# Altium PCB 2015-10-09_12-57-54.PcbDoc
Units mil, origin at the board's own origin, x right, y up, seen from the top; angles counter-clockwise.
Board outline 3100 x 2300 mil, 4 copper layers (Top Layer, MidLayer1, MidLayer2, Bottom Layer); 26 components, 13 nets, 66 pads, 301 vias.
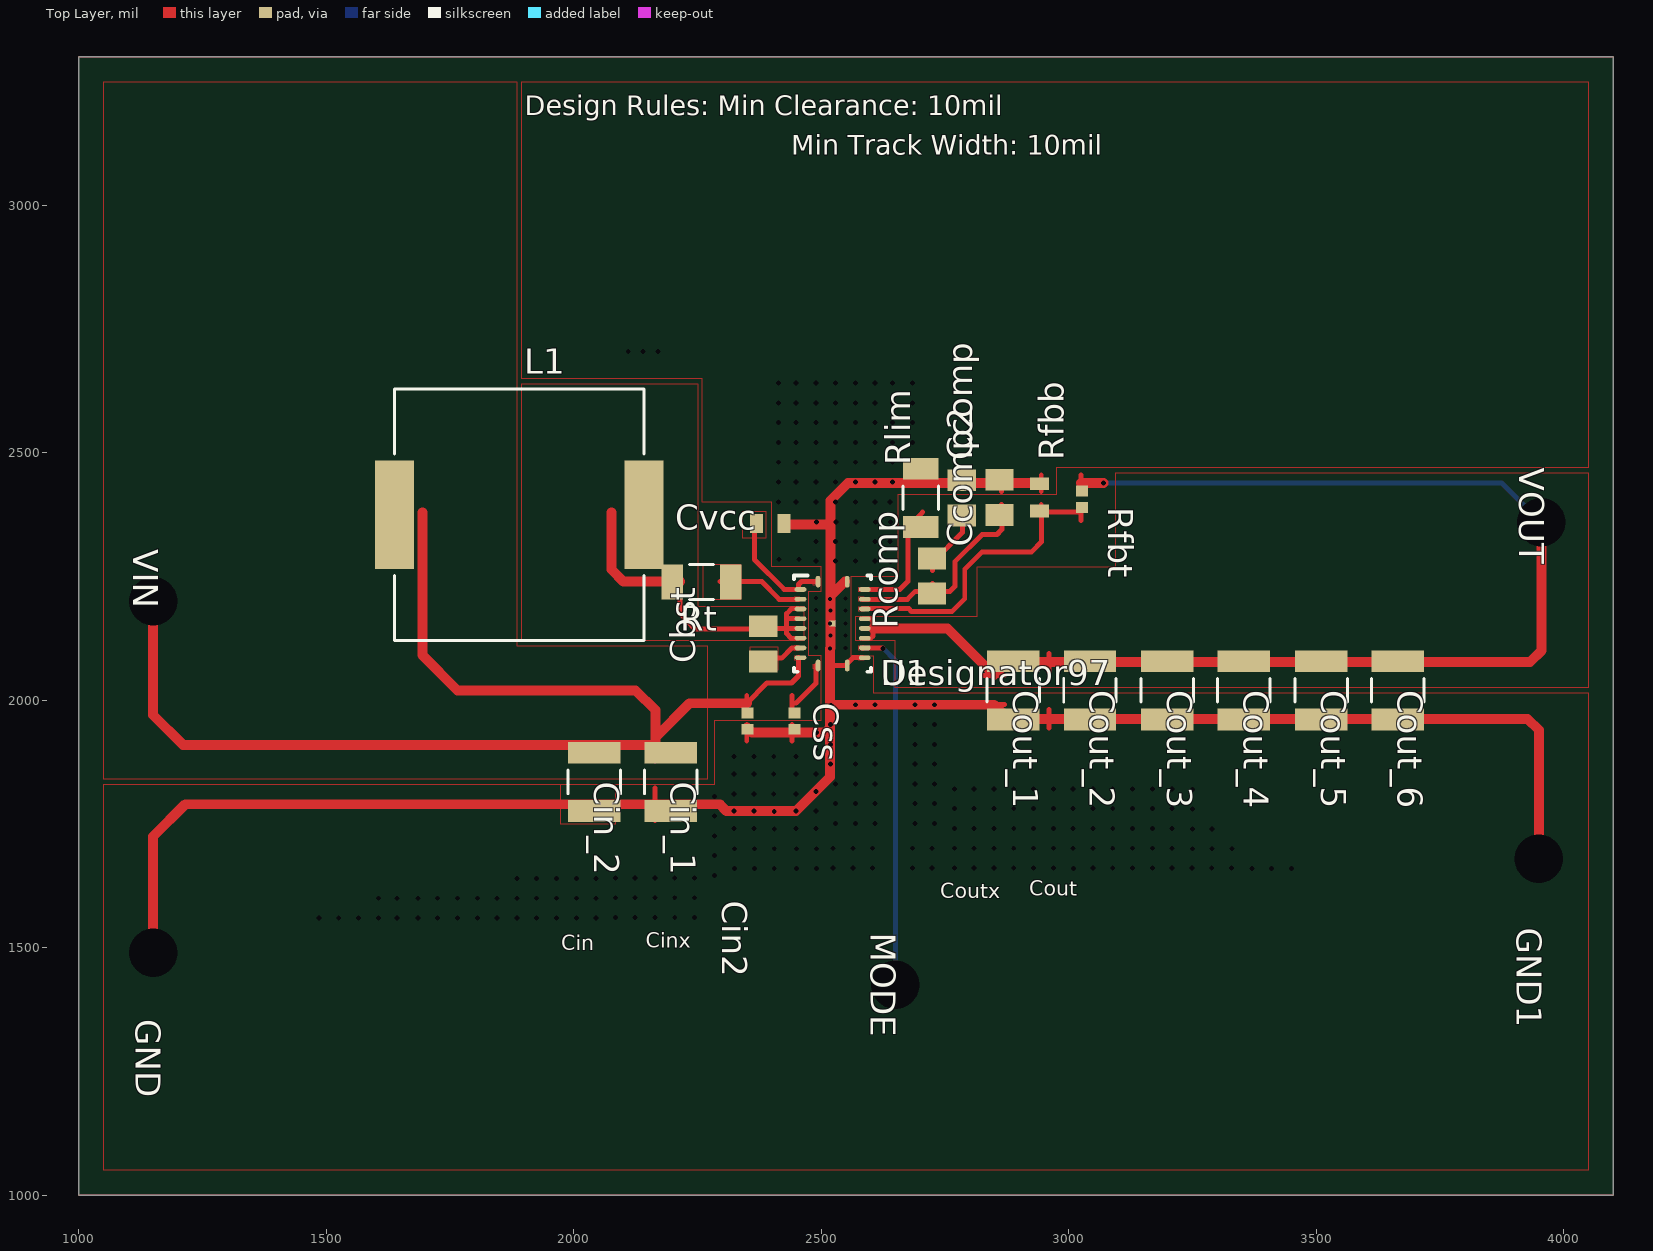
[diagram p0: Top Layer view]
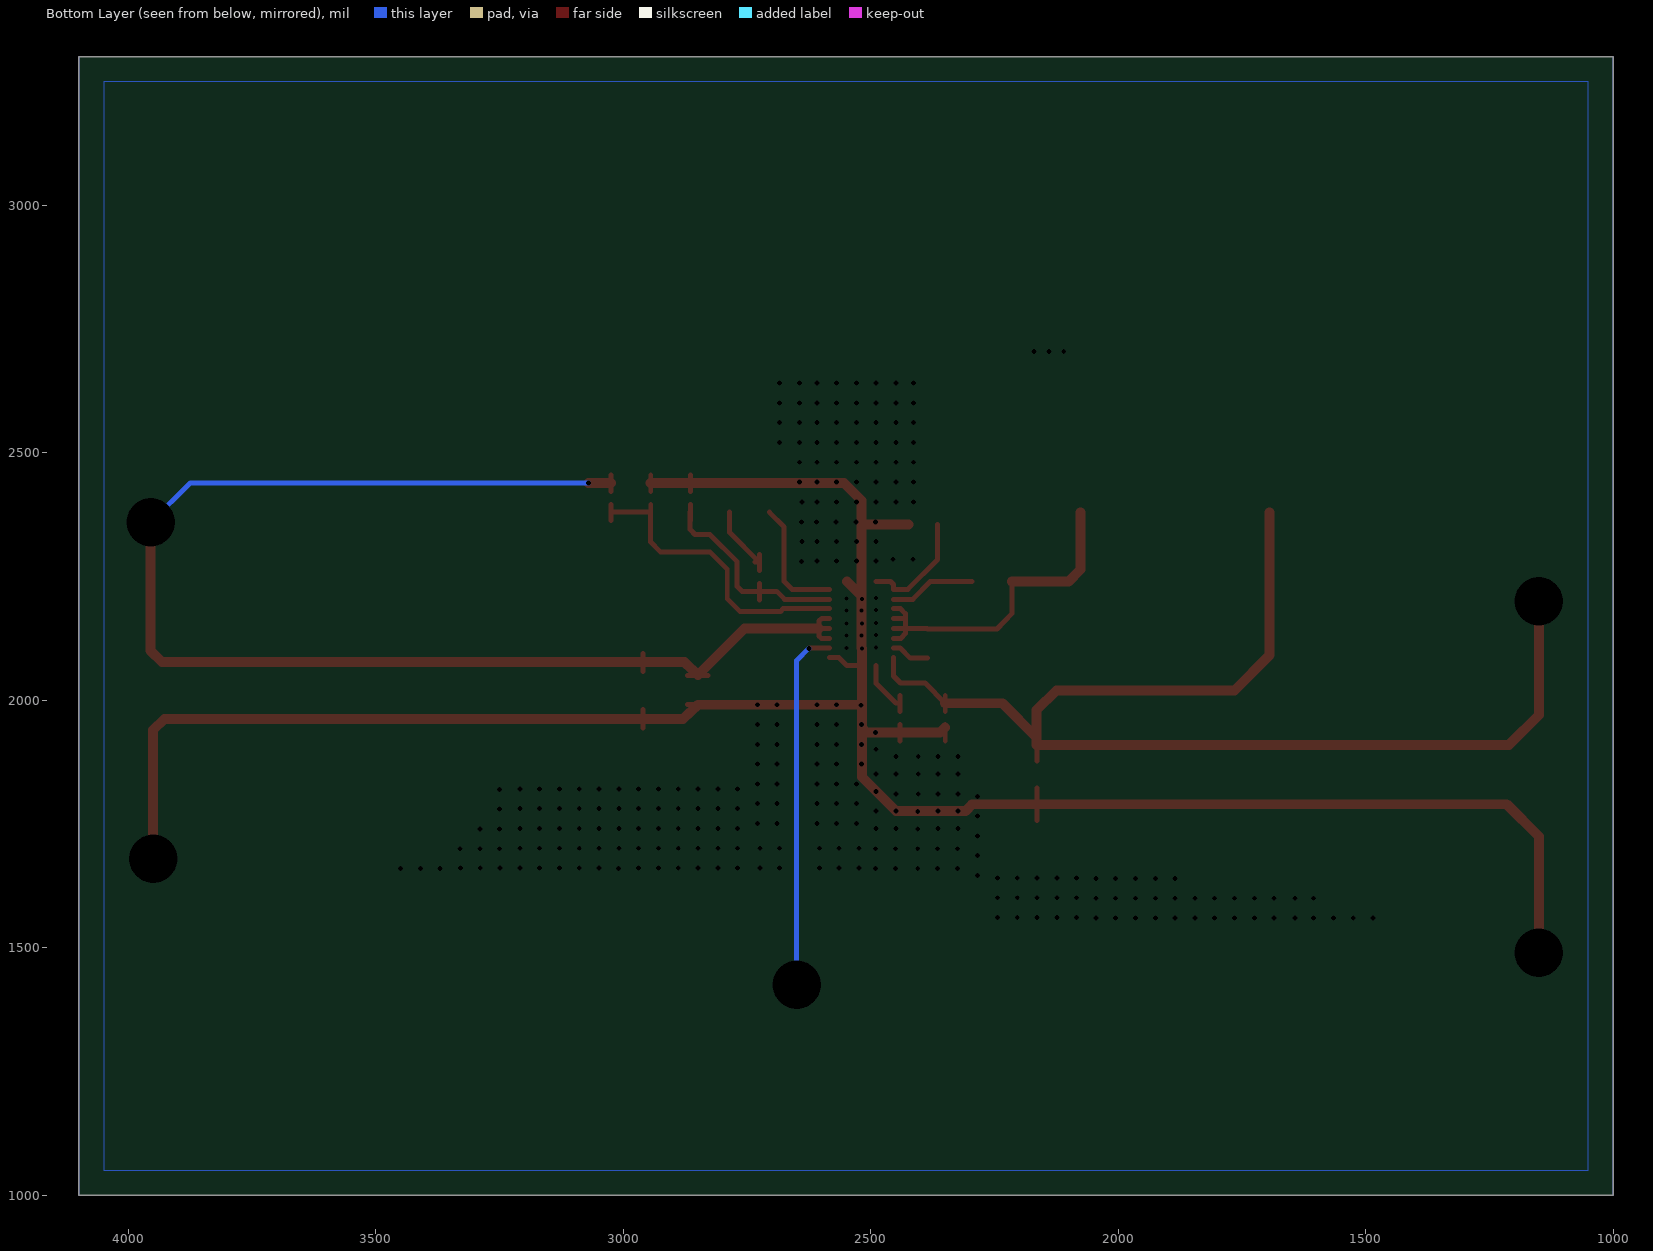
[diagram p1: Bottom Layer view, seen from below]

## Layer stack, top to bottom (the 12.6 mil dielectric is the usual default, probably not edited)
Top Layer: signal copper 1.4
Dielectric: core 12.6, FR-4, Dk 4.8
MidLayer1: signal copper 1.4
Dielectric: prepreg 12.6, FR-4, Dk 4.8
MidLayer2: signal copper 1.4
Dielectric: core 12.6, FR-4, Dk 4.8
Bottom Layer: signal copper 1.4

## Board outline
1000,1000 4100,1000 4100,3300 1000,3300

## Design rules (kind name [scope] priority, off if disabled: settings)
PlaneConnect [All] p0: scope1count=1 scope1_0_kind=Board scope1_0_value=Board scope2count=1 scope2_0_kind=Board scope2_0_value=Board commentlength=0 planeconnectstyle=Direct reliefexpansion=20 reliefentries=4 reliefconductorwidth=10 reliefairgap=10
PlaneConnect [All] p1: planeconnectstyle=Direct reliefexpansion=20 reliefentries=4 reliefconductorwidth=10 reliefairgap=10
PolygonConnect [All] p0: scope1count=1 scope1_0_kind=Board scope1_0_value=Board scope2count=1 scope2_0_kind=Board scope2_0_value=Board commentlength=0 connectstyle=Direct reliefconductorwidth=10 reliefentries=4 polygonreliefangle="90 Angle"
PolygonConnect [All] p1: connectstyle=Direct reliefconductorwidth=10 reliefentries=4 polygonreliefangle="90 Angle"

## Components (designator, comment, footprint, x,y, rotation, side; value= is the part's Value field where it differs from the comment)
Cbst "" 0805 2383,2114 r90 top
Ccomp "" 0805 2784,2409 r90 top
Ccomp2 "" 0805 2860,2410 r90 top
Cin2 "" 0402 2351,1958 r270 top
Cin_1 "" 1210 2196,1835 r270 top
Cin_2 "" 1210 2041,1835 r270 top
Cout_1 "" 1210 2888,2020 r270 top
Cout_2 "" 1210 3043,2020 r270 top
Cout_3 "" 1210 3199,2020 r270 top
Cout_4 "" 1210 3354,2020 r270 top
Cout_5 "" 1210 3510,2020 r270 top
Cout_6 "" 1210 3665,2020 r270 top
Css "" 0402 2446,1958 r270 top
Cvcc "" 1608 2397,2357 r0 top
GND "" TP-1502 1149,1490 r270 top
GND1 "" TP-1502 3948,1679 r270 top
L1 "" ETQP 1890,2375 r0 top
MODE "" TP-1502 2649,1425 r270 top
Rcomp "" 0805 2724,2251 r90 top
Rfbb "" 0603 2941,2410 r90 top
Rfbt "" 0402 3027,2406 r270 top
Rlim "" 1206 2701,2409 r90 top
Rt "" 1206 2258,2239 r0 top
U1 "" RHL0020A 2523,2155 r0 top
VIN "" TP-1502 1149,2198 r270 top
VOUT "" TP-1502 3953,2358 r270 top

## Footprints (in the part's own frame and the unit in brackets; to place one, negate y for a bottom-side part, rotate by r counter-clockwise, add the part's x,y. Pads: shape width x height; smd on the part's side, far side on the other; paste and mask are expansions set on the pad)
0402 [mil]
  rect 22x24 smd: 1(-16.5,0) 2(16.5,0)
0603 [mil]
  rect 26x38 smd: 1(-27.5,0) 2(27.5,0)
0805 [mil]
  rect 44x57 smd: 1(-35.5,0) 2(35.5,0)
1206 [mil]
  rect 44x71 smd: 1(-59,0) 2(59,0)
  silkscreen extent -24,-36 24,36
1210 [mil]
  rect 44x106 smd: 1(-59,0) 2(59,0)
  silkscreen extent -24,-53 24,53
1608 [mil]
  rect 26x38 smd: 1(-27.5,0) 2(27.5,0)
ETQP [mil]
  rect 79x220 smd: 1(-252,0) 2(252,0)
  silkscreen extent -252,-254 252,254
RHL0020A [mm]
  oval 0.24x0.6 smd: 1(-0.75,2.15) 10(-0.75,-2.15) 11(0.75,-2.15) 20(0.75,2.15)
  oval 0.6x0.24 smd: 2(-1.65,1.75) 3(-1.65,1.25) 4(-1.65,0.75) 5(-1.65,0.25) 6(-1.65,-0.25) 7(-1.65,-0.75) 8(-1.65,-1.25) 9(-1.65,-1.75) 12(1.65,-1.75) 13(1.65,-1.25) 14(1.65,-0.75) 15(1.65,-0.25) 16(1.65,0.25) 17(1.65,0.75) 18(1.65,1.25) 19(1.65,1.75)
  rect 0.3x0.3 smd: 21(0,0)
  silkscreen extent -1.98,-2.47 1.98,2.47
TP-1502 [mil]
  round 0 hole 32: 1(0,0)

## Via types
v1: diameter 0, hole 10, Top Layer to Bottom Layer, 281 vias
v2: diameter 0, hole 8, Top Layer to Bottom Layer, 15 vias
v3: diameter 0, hole 98, Top Layer to Bottom Layer, 5 vias

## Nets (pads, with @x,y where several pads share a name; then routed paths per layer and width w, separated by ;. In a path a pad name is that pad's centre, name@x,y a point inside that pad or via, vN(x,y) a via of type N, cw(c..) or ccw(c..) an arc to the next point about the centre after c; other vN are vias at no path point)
0: Ccomp2.2 Ccomp.2 Cin2.2 Cin_1.2 Cin_2.2 Cout_1.2 Cout_2.2 Cout_3.2 Cout_4.2 Cout_5.2 Cout_6.2 Css.2 Cvcc.2 GND1.1 GND.1 Rfbb.2 Rlim.2 U1.11 U1.12 U1.20 U1.21 | length 5042.3
  Top Layer w10: Cin_1.2@2164,1757 2164,1823 ; 2349.5,1918 Cin2.2@2349.5,1951 ; 2440.5,1918 Css.2@2440.5,1951 ; 2518,2070 2519,2070 2548,2070 2564,2086 U1.12@2583,2086 ; U1.21@2518.5,2153 U1.21@2518.5,2156 ; 2829,1991.5 2870,1991.5 ; 2864.5,2422 Ccomp2.2@2864.5,2455 ; 2944.5,2422 2944.5,2455 ; 2960,1944 2960,1981
  Top Layer w20: v3(1150,1490) 1150,1725 1215,1790 2030,1790 2165,1790 2295,1790 2308,1776 v1(2324,1776) v1(2364,1776) v1(2449,1776) 2518,1845 2518,1945 ; Cin2.2@2350,1945 2360,1935 2441,1935 2509,1935 2518,1945 ; Cvcc.2@2424,2355 2519,2355 ; U1.20@2548,2240 2519,2211 ; Rfbb.2@2945,2439 2865,2439 2785,2439 2705,2439 2554,2439 2519,2404 2519,2355 ; v3(3950,1680) 3950,1940 3927,1962 2960,1962 2879,1962 2849,1991 2521,1991 2518,1995 ; 2518,1945 2518,1995 ; 2518,1995 2518,2070 v2(2518,2105) 2519,2106 v2(2519,2131) v2(2519,2181) 2519,2211 ; 2519,2211 2519,2355
  other v1: 1485,1560 1525,1560 1565,1560 1605,1560 1643,1560 1685,1560 1725,1560 1765,1560 1805,1560 1845,1560 1885,1560 1925,1560 1965,1560 2005,1560 2045,1560 2084,1561 2124,1561 2164,1561 2204,1561 2244,1561 1605,1600 1643,1600 1685,1600 1725,1600 1765,1600 1805,1600 1845,1600 1885,1600 1925,1600 1965,1600 2005,1600 2045,1600 2084,1601 2124,1601 2164,1601 2204,1601 2244,1601 1885,1640 1925,1640 1965,1640 2005,1640 2045,1640 2084,1641 2124,1641 2164,1641 2204,1641 2244,1641 2284,1646 2325,1660 2365,1660 2405,1660 2450,1660 2490,1660 3010,1660 3370,1660 3410,1660 3450,1660 2524,1661 2564,1661 2604,1661 2684,1661 2724,1661 2769,1661 2809,1661 2849,1661 2889,1661 2929,1661 2969,1661 3049,1661 3089,1661 3129,1661 3169,1661 3209,1661 3249,1661 3289,1661 3329,1661 2284,1686 2325,1700 2365,1700 2405,1700 2450,1700 2490,1700 3250,1700 3290,1700 3330,1700 2524,1701 2564,1701 2604,1701 2684,1701 2724,1701 2769,1701 2809,1701 2849,1701 2889,1701 2929,1701 2969,1701 3009,1701 3049,1701 3089,1701 3129,1701 3169,1701 3209,1701 2284,1726 2405,1740 3250,1740 3290,1740 2324,1741 2364,1741 2449,1741 2489,1741 2769,1741 2809,1741 2849,1741 2889,1741 2929,1741 2969,1741 3009,1741 3049,1741 3089,1741 3129,1741 3169,1741 3209,1741 2529,1751 2569,1751 2609,1751 2689,1751 2729,1751 2284,1766 2405,1775 2489,1776 3250,1780 2769,1781 2809,1781 2849,1781 2889,1781 2929,1781 2969,1781 3009,1781 3049,1781 3089,1781 3129,1781 3169,1781 3209,1781 2529,1791 2569,1791 2609,1791 2689,1791 2729,1791 2284,1806 2324,1811 2364,1811 2404,1811 2449,1811 2489,1816 3250,1820 2769,1821 2809,1821 2849,1821 2889,1821 2929,1821 2969,1821 3009,1821 3049,1821 3089,1821 3129,1821 3169,1821 3209,1821 2529,1831 2569,1831 2609,1831 2689,1831 2729,1831 2324,1851 2364,1851 2404,1851 2449,1851 2489,1851 2519,1871 2569,1871 2609,1871 2689,1871 2729,1871 2324,1886 2364,1886 2404,1886 2449,1886 2489,1901 2519,1911 2569,1911 2609,1911 2689,1911 2729,1911 2490,1935 2519,1951 2569,1951 2609,1951 2689,1951 2729,1951 2520,1990 2569,1991 2609,1991 2689,1991 2729,1991 2640,2280 2489,2281 2529,2281 2569,2281 2609,2281 2415,2285 2455,2285 2489,2321 2529,2321 2569,2321 2609,2321 2639,2321 2490,2360 2530,2360 2570,2360 2610,2360 2640,2360 2414,2401 2449,2401 2489,2401 2529,2401 2569,2401 2609,2401 2639,2401 2414,2441 2449,2441 2489,2441 2529,2441 2569,2441 2609,2441 2644,2441 2414,2481 2449,2481 2489,2481 2529,2481 2569,2481 2609,2481 2644,2481 2414,2521 2449,2521 2489,2521 2529,2521 2569,2521 2609,2521 2644,2521 2684,2521 2414,2561 2449,2561 2489,2561 2529,2561 2569,2561 2609,2561 2644,2561 2684,2561 2414,2601 2449,2601 2489,2601 2529,2601 2569,2601 2609,2601 2644,2601 2684,2601 2414,2641 2449,2641 2489,2641 2529,2641 2569,2641 2609,2641 2644,2641 2684,2641 2110,2705 2140,2705 2170,2705
  other v2: 2549,2106 2489,2107 2549,2131 2489,2132 2518,2155 2549,2155 2489,2156 2549,2181 2489,2182 2518,2205 2549,2206 2489,2207
1: Cin2.1 Cin_1.1 Cin_2.1 L1.1 U1.9 VIN.1 | length 2637.5
  Top Layer w10: Cin_1.1@2164,1877 2164,1943 ; Cin2.1@2349.5,1977 2349.5,2010 ; 2350,1994 2390,2035 2440,2035 2454,2049 U1.9@2454,2086
  Top Layer w20: v3(1150,2200) 1150,1970 1210,1910 Cin_1.1@2165,1910 ; 1694,2380 1694,2091 1765,2020 2125,2020 2165,1980 Cin_1.1@2165,1910 ; 2350,1994 2234,1994 2165,1925 Cin_1.1@2165,1910
2: Cvcc.1 U1.1 U1.2 | length 232.3
  Top Layer w10: Cvcc.1@2365,2355 2365,2284 2425,2224 2454,2224 2454,2234 2460,2240 U1.1@2489,2240
3: Ccomp2.1 Rcomp.1 U1.18 | length 470.7
  Top Layer w10: U1.18@2583,2204 2674,2204 2690,2220 2725,2220 2760,2220 2770,2230 2770,2280 2825,2335 2855,2335 2865,2345 Ccomp2.1@2865,2380 ; Rcomp.1@2724.5,2203 Rcomp.1@2724.5,2236 ; Ccomp2.1@2864.5,2363 Ccomp2.1@2864.5,2396
5: Ccomp.1 Rcomp.2 | length 167.9
  Top Layer w10: 2724.5,2262 Rcomp.2@2724.5,2295 ; Rcomp.2@2734,2279 2725,2279 2785,2339 Ccomp.1@2785,2380
7: Rfbb.1 Rfbt.2 U1.17 | length 664.4
  Top Layer w10: U1.17@2583,2185 2677,2185 2682,2179 2764,2179 2790,2205 2790,2265 2825,2300 2925,2300 2945,2320 2945,2380 Rfbt.2@3025,2380 ; 2944.5,2363 2944.5,2396 ; 3024.5,2363 Rfbt.2@3024.5,2396
8: Cout_1.1 Cout_2.1 Cout_3.1 Cout_4.1 Cout_5.1 Cout_6.1 Rfbt.1 U1.14 U1.15 U1.16 VOUT.1 | length 2842.3
  Top Layer w10: U1.14@2583,2125 2600,2125 2605,2130 2605,2145 ; U1.15@2583,2145 2605,2145 ; U1.16@2583,2165 2599,2165 2605,2160 2605,2145 ; 2829,2050.5 2870,2050.5 ; 2960,2058 2960,2095 ; Rfbt.1@3024.5,2422 3024.5,2455
  Top Layer w20: 2605,2145 2755,2145 2849,2051 2876,2077 2960,2077 3932,2077 3955,2100 v3(3955,2360) ; 3025,2439 v1(3070,2439)
  Bottom Layer w10: v1(3070,2439) 3875,2439 v3(3955,2360)
9: Cbst.2 L1.2 Rt.1 U1.4 U1.5 U1.6 U1.7 | length 703.1
  Top Layer w10: Rt.1@2215,2240 2215,2175 2245,2144 2385,2144 2386,2145 2430,2145 ; U1.7@2454,2125 2439,2125 2430,2135 2430,2145 ; U1.6@2454,2145 2430,2145 ; U1.5@2454,2165 2430,2165 ; U1.4@2454,2185 2440,2185 2430,2175 2430,2165 ; 2430,2145 2430,2165
  Top Layer w20: 2076,2380 2076,2264 2100,2240 Rt.1@2215,2240
11: Rlim.1 U1.19 | length 251.1
  Top Layer w10: U1.19@2583,2224 2659,2224 2675,2240 2675,2350 2705,2380
14: Css.1 U1.10 | length 133.6
  Top Layer w10: Css.1@2440.5,1977 2440.5,2010 ; 2441,1994 2449,1994 2489,2034 U1.10@2489,2070
15: Cbst.1 U1.8 | length 77.7
  Top Layer w10: Cbst.1@2385,2085 2420,2085 2441,2106 U1.8@2454,2106
16: Rt.2 U1.3 | length 174.2
  Top Layer w10: Rt.2@2295,2240 2380,2240 2415,2204 U1.3@2454,2204
22: MODE.1 U1.13 | length 732.6
  Top Layer w10: U1.13@2583,2106 2623,2106 v1(2625,2105)
  Bottom Layer w10: v1(2625,2105) 2650,2080 v3(2650,1425)

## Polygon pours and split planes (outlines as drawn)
2 on Top Layer " " (solid, pour order 0): 2341,2327 2341,2382 2388,2382 2388,2327
2 on Top Layer " " (solid, pour order 1): 2484,2232 2484,2242 2493,2242 2493,2232
11 on Top Layer " " (solid, pour order 2): 2576,2219 2576,2228 2586,2228 2586,2219
3 on Top Layer " " (solid, pour order 3): 2576,2200 2576,2209 2586,2209 2586,2200
7 on Top Layer " " (solid, pour order 4): 2576,2180 2576,2189 2586,2189 2586,2180
22 on Top Layer " " (solid, pour order 5): 2576,2101 2576,2110 2586,2110 2586,2101
14 on Top Layer " " (solid, pour order 6): 2484,2064 2484,2073 2493,2073 2493,2064
1 on Top Layer " " (solid, pour order 7): 2446,2081 2446,2090 2456,2090 2456,2081
15 on Top Layer " " (solid, pour order 8): 2446,2101 2446,2110 2456,2110 2456,2101
16 on Top Layer " " (solid, pour order 9): 2446,2200 2446,2209 2456,2209 2456,2200
2 on Top Layer " " (solid, pour order 10): 2446,2219 2446,2228 2456,2228 2456,2219
16 on Top Layer " " (solid, pour order 11): 2262,2203 2262,2275 2337,2275 2337,2203
15 on Top Layer " " (solid, pour order 12): 2357,2061 2357,2108 2412,2108 2412,2061
1 on Top Layer " " (solid, pour order 13): 1885,3250 1885,2110 2270,2110 2270,1840 1050,1840 1050,3250
9 on Top Layer " " (solid, pour order 14): 1895,2120 1895,2640 2250,2640 2250,2190 2465,2190 2465,2120
8 on Top Layer " " (solid, pour order 15): 2570,2120 2570,2170 2815,2170 2815,2270 3095,2270 3095,2460 4050,2460 4050,2025 2650,2025 2650,2120
0 on Top Layer " " (solid, pour order 16): 2576,2081 2576,2090 2586,2090 2586,2081
0 on Top Layer " " (solid, pour order 17): 1974,1750 1974,1830 2084,1830 2084,1750
0 on Top Layer " " (solid, pour order 19): 2285,1960 2500,1960 2500,2090 2475,2090 2475,2220 2500,2220 2500,2270 2400,2270 2400,2400 2260,2400 2260,2650 1895,2650 1895,3250 4050,3250 4050,2470 2975,2470 2975,2415 2655,2415 2655,2250 2560,2250 2560,2090 2605,2090 2605,2015 4050,2015 4050,1050 1050,1050 1050,1830 2285,1830
0 on Bottom Layer " " (solid, pour order 18): 1050,1050 1050,3250 4050,3250 4050,1050

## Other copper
Multi-Layer:
  the board outline again, w1

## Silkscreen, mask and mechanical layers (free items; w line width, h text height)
Top Overlay:
  text "Design Rules: Min Clearance: 10mil" at 1901,3182 h40
  text "Min Track Width: 10mil" at 2439,3102 h40
  text "Cout" at 2920,1605 h30
  text "Coutx" at 2740,1600 h30
  text "Cinx" at 2145,1500 h30
  text "Cin" at 1975,1495 h30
